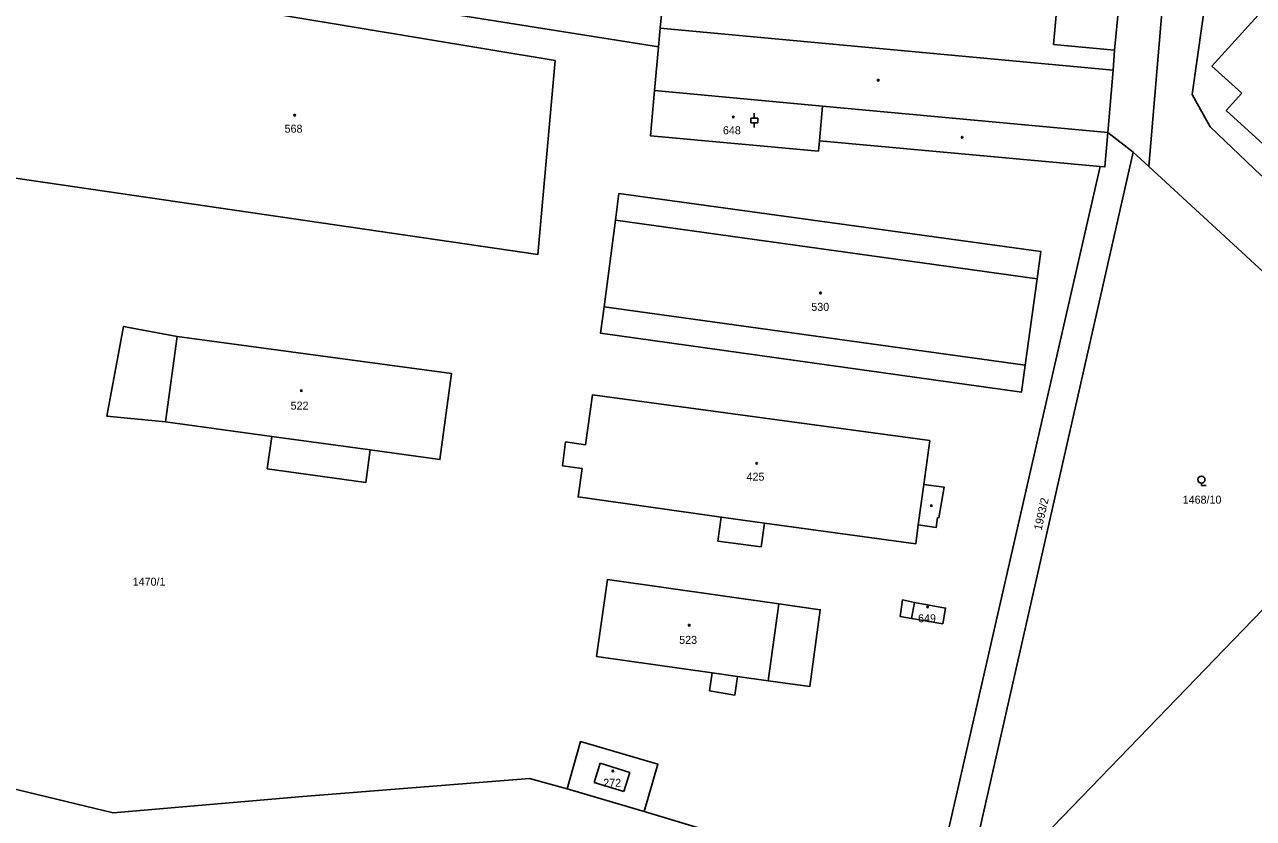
# Model space of a CAD drawing. Extents: x -793666 to -785424, y -1118958 to -1108761.
# Drawn here: x -788273.7 to -788012.6, y -1117098.1 to -1116929.5 of the extents above; entities that cross this region are included whole.
import ezdxf

# ---------------------------------------------------------------- set-up
doc = ezdxf.new("R2010")
doc.units = 0
for name, color, linetype in [('Hranice parcel', 7, 'Continuous'), ('Parcelní čísla', 7, 'Continuous'), ('Vnitřní kresba', 7, 'Continuous'), ('Značky budov', 7, 'Continuous'), ('Značky kultur', 7, 'Continuous')]:
    doc.layers.add(name, color=color, linetype=linetype)

msp = doc.modelspace()

# ---------------------------------------------------------------- linework, layer by layer
at = {"layer": 'Hranice parcel'}
for p, q in [((-788031.28, -1116917.52), (-788034.85, -1116959.6)), ((-788139.02, -1116934.24), (-788201.1, -1116924.39)), ((-788139.86, -1116943.51), (-788139.02, -1116934.24)), ((-788043.54, -1116952.39), (-788038.17, -1116956.55)), ((-788038.17, -1116956.55), (-788075.38, -1117120.72)), ((-788034.85, -1116959.6), (-788038.17, -1116956.55)), ((-788034.85, -1116959.6), (-788007.01, -1116985.23)), ((-787974.15, -1117015.9), (-788075.38, -1117120.72)), ((-788166.43, -1117089.58), (-788158.42, -1117091.8)), ((-788142.07, -1117096.6), (-788158.42, -1117091.8)), ((-788142.07, -1117096.6), (-788114.78, -1117104.76))]:
    msp.add_line(p, q, dxfattribs=at)
for points in [[(-788144.03, -1116829.23), (-788134.59, -1116831.38), (-788136.85, -1116860), (-788137.18, -1116868.51), (-788137.26, -1116874.52), (-788133.28, -1116874.91), (-788138.4, -1116927.32), (-788138.66, -1116930.26), (-788139.02, -1116934.24)], [(-788043.54, -1116952.39), (-788042.44, -1116939.2), (-788042.09, -1116934.95), (-788036.25, -1116874.48)], [(-788024.5, -1116914.01), (-788021.36, -1116914.26), (-788025.63, -1116944.35), (-788021.8, -1116951.18), (-788010.97, -1116961.52), (-788000.13, -1116964.06), (-787981.26, -1116937.26), (-787984.02, -1116928.1), (-788016.7, -1116897.93)], [(-788160.99, -1116937.11), (-788164.62, -1116978.28), (-788284.44, -1116960.86), (-788274.96, -1116918.14), (-788160.99, -1116937.11)], [(-788045.15, -1116959.61), (-788104.79, -1116954.2), (-788104.99, -1116956.34), (-788140.73, -1116953.1), (-788139.86, -1116943.51)], [(-788139.86, -1116943.51), (-788104.14, -1116946.8), (-788043.54, -1116952.39)], [(-788045.15, -1116959.61), (-788044.15, -1116959.7), (-788043.54, -1116952.39)], [(-788081.69, -1117119.18), (-788081.68, -1117119.13), (-788081.44, -1117118.1), (-788056.69, -1117010.01), (-788045.15, -1116959.61)], [(-788061.09, -1117001.82), (-788061.89, -1117007.57), (-788151.31, -1116995.05), (-788150.57, -1116989.4), (-788148.16, -1116971.04), (-788147.42, -1116965.39), (-788057.75, -1116977.69), (-788058.55, -1116983.46), (-788061.09, -1117001.82)], [(-788252.69, -1116993.58), (-788241.31, -1116995.74), (-788182.96, -1117003.62), (-788185.44, -1117021.87), (-788200.24, -1117019.79), (-788201.18, -1117026.7), (-788222.14, -1117023.8), (-788221.2, -1117016.94), (-788243.76, -1117013.86), (-788256.19, -1117012.67), (-788252.69, -1116993.58)], [(-788117.21, -1117040.43), (-788126.37, -1117039.18), (-788125.67, -1117034.08), (-788156.09, -1117029.8), (-788155.24, -1117023.77), (-788159.41, -1117023.18), (-788158.74, -1117018.11), (-788154.52, -1117018.7), (-788153.02, -1117008.12), (-788081.39, -1117017.84), (-788082.65, -1117027.15), (-788078.31, -1117027.74), (-788079.44, -1117034.23), (-788079.73, -1117034.19), (-788080.01, -1117036.27), (-788083.81, -1117035.76), (-788084.35, -1117039.75), (-788116.51, -1117035.34), (-788117.21, -1117040.43)], [(-788128.14, -1117071), (-788127.59, -1117067.16), (-788152.15, -1117063.66), (-788149.86, -1117047.34), (-788113.46, -1117052.53), (-788104.64, -1117053.76), (-788106.88, -1117070.08), (-788115.73, -1117068.85), (-788122.23, -1117067.92), (-788122.79, -1117071.88), (-788128.14, -1117071)], [(-788078.61, -1117056.76), (-788085.22, -1117055.62), (-788087.69, -1117055.19), (-788087.16, -1117051.68), (-788084.65, -1117052.19), (-788078.01, -1117053.42), (-788078.61, -1117056.76)], [(-788320.78, -1117080.88), (-788298.06, -1117086.45), (-788260.74, -1117095.5), (-788254.91, -1117096.92), (-788214.58, -1117093.41), (-788166.43, -1117089.58)], [(-788158.42, -1117091.8), (-788155.61, -1117081.77), (-788139.14, -1117086.58), (-788142.07, -1117096.6)]]:
    msp.add_lwpolyline(points, dxfattribs=at)
at = {"layer": 'Vnitřní kresba'}
for p, q in [((-788055.1, -1116933.69), (-788049.79, -1116874.59)), ((-788021.44, -1116938.28), (-788001.97, -1116916.91)), ((-788042.44, -1116939.2), (-788138.66, -1116930.26)), ((-788042.09, -1116934.95), (-788055.1, -1116933.69)), ((-788015.06, -1116944.05), (-788021.44, -1116938.28)), ((-788018.41, -1116947.76), (-788015.06, -1116944.05)), ((-788104.14, -1116946.8), (-788104.79, -1116954.2)), ((-788006.09, -1116958.97), (-788018.41, -1116947.76)), ((-788148.16, -1116971.04), (-788058.55, -1116983.46)), ((-788061.09, -1117001.82), (-788150.57, -1116989.4)), ((-788241.31, -1116995.74), (-788243.76, -1117013.86)), ((-788221.2, -1117016.94), (-788200.24, -1117019.79)), ((-788082.65, -1117027.15), (-788083.81, -1117035.76)), ((-788125.67, -1117034.08), (-788116.51, -1117035.34)), ((-788085.22, -1117055.62), (-788084.65, -1117052.19)), ((-788113.46, -1117052.53), (-788115.73, -1117068.85)), ((-788127.59, -1117067.16), (-788122.23, -1117067.92)), ((-788151.37, -1117086.36), (-788152.69, -1117090.42)), ((-788145.12, -1117088.32), (-788151.37, -1117086.36)), ((-788146.37, -1117092.37), (-788145.12, -1117088.32)), ((-788152.69, -1117090.42), (-788146.37, -1117092.37))]:
    msp.add_line(p, q, dxfattribs=at)
at = {"layer": 'Značky budov'}
for centre in [(-788092.33, -1116941.3), (-788216.3, -1116948.72), (-788123.11, -1116949.12), (-788074.49, -1116953.42), (-788104.58, -1116986.49), (-788214.89, -1117007.23), (-788118.14, -1117022.66), (-788081.03, -1117031.64), (-788081.83, -1117053.19), (-788132.48, -1117057.04), (-788148.7, -1117087.99)]:
    msp.add_circle(centre, 0.175, dxfattribs=at)
at = {"layer": 'Značky kultur'}
for p, q in [((-788119.4, -1116949.33), (-788117.9, -1116949.33)), ((-788119.4, -1116950.33), (-788119.4, -1116949.33)), ((-788119.4, -1116950.33), (-788117.9, -1116950.33)), ((-788118.65, -1116949.33), (-788118.65, -1116948.33)), ((-788118.65, -1116951.33), (-788118.65, -1116950.33)), ((-788117.9, -1116950.33), (-788117.9, -1116949.33)), ((-788023.65, -1117026.88), (-788023.65, -1117027.38)), ((-788023.65, -1117027.38), (-788022.65, -1117027.38))]:
    msp.add_line(p, q, dxfattribs=at)
msp.add_circle((-788023.65, -1117026.13), 0.75, dxfattribs=at)

# ---------------------------------------------------------------- texts
at = {"layer": 'Parcelní čísla'}
for s, p in [('568', (-788218.45, -1116952.44)), ('648', (-788125.32, -1116952.78)), ('530', (-788106.54, -1116990.28)), ('522', (-788217.17, -1117011.26)), ('425', (-788120.3, -1117026.35)), ('1468/10', (-788027.63, -1117031.23)), ('1470/1', (-788250.72, -1117048.64)), ('649', (-788083.86, -1117056.42)), ('523', (-788134.61, -1117061.01)), ('272', (-788150.75, -1117091.36))]:
    msp.add_text(s, height=1.7, dxfattribs=at).set_placement(p)
msp.add_text('1993/2', height=1.7, rotation=77, dxfattribs=at).set_placement((-788057.64, -1117036.99))

doc.saveas('drawing.dxf')
